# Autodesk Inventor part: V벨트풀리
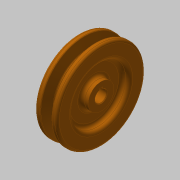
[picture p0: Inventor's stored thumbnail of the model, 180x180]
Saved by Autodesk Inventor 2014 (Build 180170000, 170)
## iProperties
Created: 2015-11
Part Number: V벨트풀리
Material: 알루미늄 6061
Document SubType Name: Modeling
Designer: mduedu
Density: 1 g/cm^3
Appearance: Orange
Author: mduedu
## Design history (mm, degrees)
sketch "스케치1"
  geometry: L1 (-9.5, 0)-(9.5, 0); L2 (0, 0)-(0, 37.7); L3 (-4.825, 37.7)-(-9.5, 37.7); L4 (-9.5, 37.7)-(-9.5, 0); L5 (0, 28.7)-(-2.074, 28.7); L6 (-2.074, 28.7)-(-4.825, 37.7); L7 (4.825, 37.7)-(9.5, 37.7); L8 (9.5, 37.7)-(9.5, 0); L9 (0, 28.7)-(2.074, 28.7); L10 (2.074, 28.7)-(4.825, 37.7); L11 (-9.5, 35)-(9.5, 35); 3 further points
  constraints: 22 end point, 7 point on line, 4 perpendicular, 3 symmetric about line, 1 coincident, 1 horizontal, 1 horizontal alignment, 1 midpoint, 1 vertical
  dimensions: "d0" = 19 distance of L1.start L1.end; "d2" = 75.4 diameter of L2.end L1 (derived); "d3" = 34 deg angle of L10 L6; "d4" = 6.3 distance between parallel lines of L11 L9; "d5" = 2.7 distance between parallel lines of L7 L11; "d6" = 8 distance of point (4, 35) point (-4, 35); "d7" = 70 diameter of L11 L1
revolve "회전1" sketch "스케치1" stored, may be unused: angle "d8" = 90 deg
sketch "스케치2"
  geometry: C1 r 24 at (0, 0); C2 r 11 at (0, 0); 1 further point
  constraints: 2 centre point, 2 coincident
  dimensions: "d9" = 48 diameter of C1; "d10" = 22 diameter of C2
extrude "돌출1" cut sketch "스케치2" distance "d11" = 6; taper "d12" = 0 deg
fillet "모깎기1" dims "d13" = 3
fillet "모깎기2" dims "d14" = 3
fillet "모깎기3" dims "d15" = 1, "d16" = 0.5, "d17" = 2
hole "구멍1" diameter "d20" = 10; stored, may be unused: countersink angle "d24" = 90 deg, drill point angle "d26" = 118 deg; dims "d18" = 10, "d19" = 10, "d21" = 6, "d22" = 4, "d23" = 2, "d25" = 8
sketch "스케치3"
  geometry: L1 (-1.5, 0)-(1.5, 0); L2 (1.5, 0)-(1.5, 6.4); L3 (1.5, 6.4)-(-1.5, 6.4); L4 (-1.5, 6.4)-(-1.5, 0); 2 further points
  constraints: 8 end point, 2 parallel, 1 coincident, 1 horizontal, 1 midpoint, 1 perpendicular
  dimensions: "d27" = 3 distance of L2.end L3.end; "d29" = 6.4 distance of L3.end L1.start
extrude "돌출2" cut sketch "스케치3" stored distance "d30" = 6; taper "d31" = 0 deg
chamfer "모따기1" distance "d32" = 0.5; stored, may be unused: second distance "d33" = 2, angle "d34" = 45 deg
node "솔리드1"
mirror "대칭1"
